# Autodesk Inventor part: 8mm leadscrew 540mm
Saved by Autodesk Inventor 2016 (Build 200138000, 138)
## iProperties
Created: 2016-01
Part Number: 8mm leadscrew 540mm
Material: Generic
Document SubType Name: Modeling
Designer: John
Density: 1 g/cm^3
Appearance: Default
Author: John
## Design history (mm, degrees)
feature "BOSS-EXTRUDE1"
body "Solid1"
